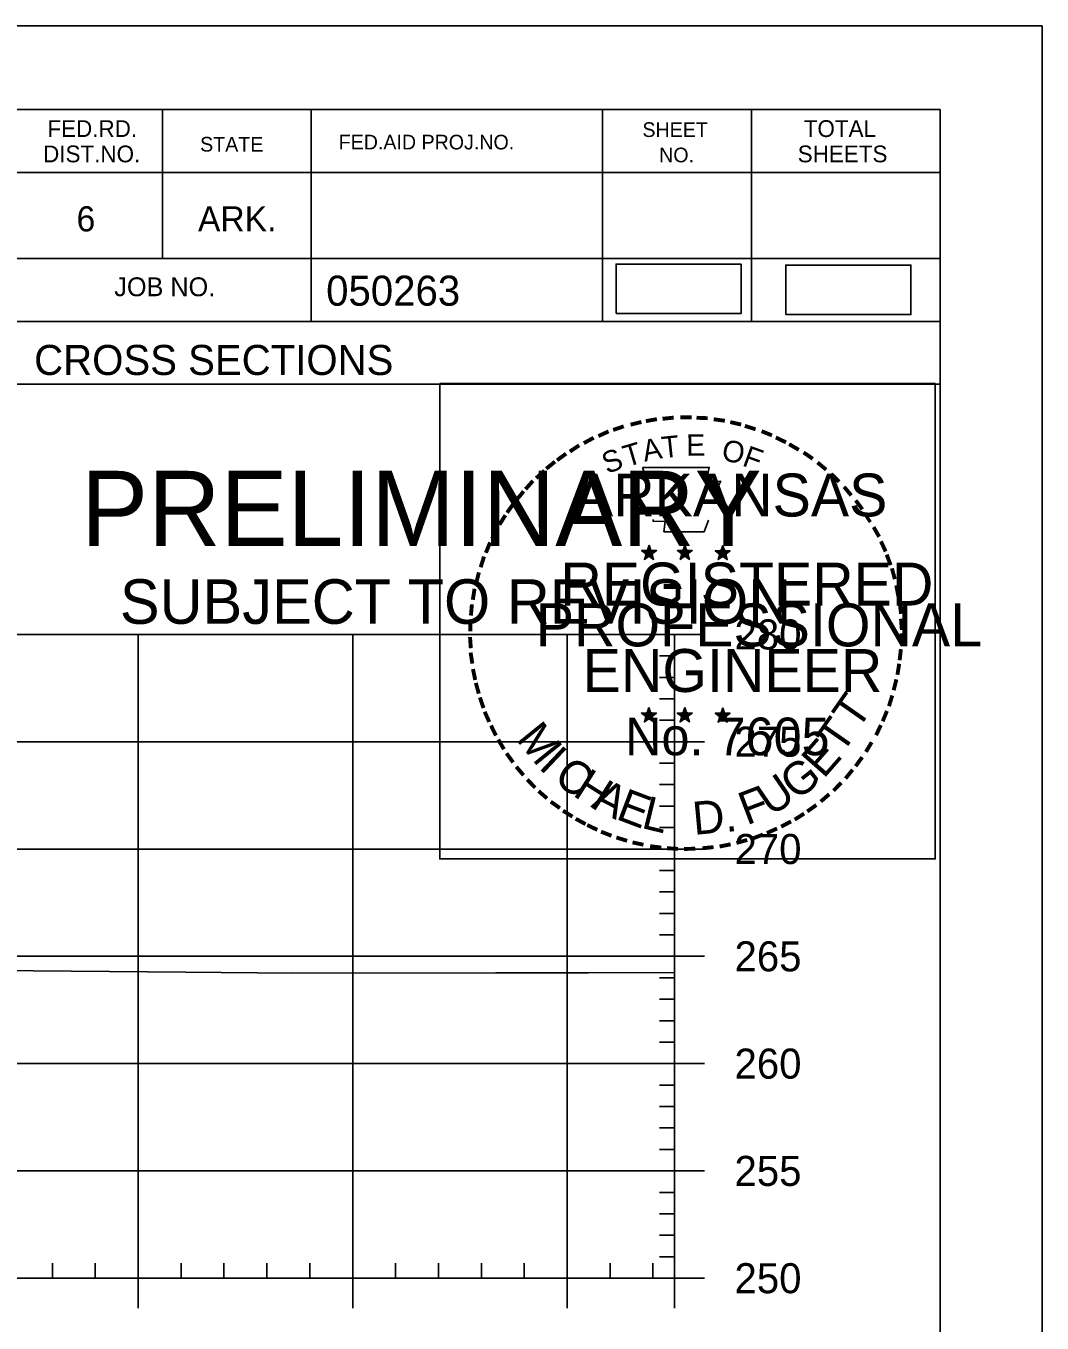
# Model space of a CAD drawing. Extents: x 1365647 to 1367999, y 387113 to 400173.
# Drawn here: x 1366009.7 to 1366057, y 388379 to 388439.4 of the extents above; entities that cross this region are included whole.
import ezdxf

# ---------------------------------------------------------------- set-up
doc = ezdxf.new("R2010")
doc.units = 0
for name, color, linetype in [('R_Axis', 7, 'Continuous'), ('R_Axis Annot', 7, 'Continuous'), ('R_Border', 7, 'Continuous'), ('R_Border PE', 7, 'Continuous'), ('R_Border Prem', 7, 'Continuous'), ('R_Detour', 7, 'Continuous'), ('R_Exist Surface', 7, 'Continuous'), ('R_Grid', 7, 'Continuous'), ('R_No Plot', 7, 'Continuous')]:
    doc.layers.add(name, color=color, linetype=linetype)

msp = doc.modelspace()

# ---------------------------------------------------------------- linework, layer by layer
at = {"layer": 'R_Axis'}
for p, q in [((1366039.888, 388381.069), (1366039.888, 388411.069)), ((1366041.288, 388411.069), (1366039.888, 388411.069)), ((1366039.888, 388410.069), (1366039.188, 388410.069)), ((1366039.888, 388409.069), (1366039.188, 388409.069)), ((1366039.888, 388408.069), (1366039.188, 388408.069)), ((1366039.888, 388407.069), (1366039.188, 388407.069)), ((1366041.288, 388406.069), (1366039.888, 388406.069)), ((1366039.888, 388405.069), (1366039.188, 388405.069)), ((1366039.888, 388404.069), (1366039.188, 388404.069)), ((1366039.888, 388403.069), (1366039.188, 388403.069)), ((1366039.888, 388402.069), (1366039.188, 388402.069)), ((1366041.288, 388401.069), (1366039.888, 388401.069)), ((1366039.888, 388400.069), (1366039.188, 388400.069)), ((1366039.888, 388399.069), (1366039.188, 388399.069)), ((1366039.888, 388398.069), (1366039.188, 388398.069)), ((1366039.888, 388397.069), (1366039.188, 388397.069)), ((1366041.288, 388396.069), (1366039.888, 388396.069)), ((1366039.888, 388395.069), (1366039.188, 388395.069)), ((1366039.888, 388394.069), (1366039.188, 388394.069)), ((1366039.888, 388393.069), (1366039.188, 388393.069)), ((1366039.888, 388392.069), (1366039.188, 388392.069)), ((1366041.288, 388391.069), (1366039.888, 388391.069)), ((1366039.888, 388390.069), (1366039.188, 388390.069)), ((1366039.888, 388389.069), (1366039.188, 388389.069)), ((1366039.888, 388388.069), (1366039.188, 388388.069)), ((1366039.888, 388387.069), (1366039.188, 388387.069)), ((1366041.288, 388386.069), (1366039.888, 388386.069)), ((1366039.888, 388385.069), (1366039.188, 388385.069)), ((1366039.888, 388384.069), (1366039.188, 388384.069)), ((1366039.888, 388383.069), (1366039.188, 388383.069)), ((1366039.888, 388382.069), (1366039.188, 388382.069)), ((1366010.888, 388381.069), (1366010.888, 388381.769)), ((1366012.888, 388381.069), (1366012.888, 388381.769)), ((1366016.888, 388381.069), (1366016.888, 388381.769)), ((1366018.888, 388381.069), (1366018.888, 388381.769)), ((1366020.888, 388381.069), (1366020.888, 388381.769)), ((1366022.888, 388381.069), (1366022.888, 388381.769)), ((1366026.888, 388381.069), (1366026.888, 388381.769)), ((1366028.888, 388381.069), (1366028.888, 388381.769)), ((1366030.888, 388381.069), (1366030.888, 388381.769)), ((1366032.888, 388381.069), (1366032.888, 388381.769)), ((1366036.888, 388381.069), (1366036.888, 388381.769)), ((1366038.888, 388381.069), (1366038.888, 388381.769)), ((1365749.888, 388381.069), (1366039.888, 388381.069)), ((1366014.888, 388379.669), (1366014.888, 388381.069)), ((1366024.888, 388379.669), (1366024.888, 388381.069)), ((1366034.888, 388379.669), (1366034.888, 388381.069)), ((1366039.888, 388379.669), (1366039.888, 388381.069)), ((1366041.288, 388381.069), (1366039.888, 388381.069))]:
    msp.add_line(p, q, dxfattribs=at)
at = {"layer": 'R_Border'}
for p, q in [((1365736.095, 388435.529), (1366052.275, 388435.529)), ((1366016.015, 388435.529), (1366016.015, 388428.589)), ((1366022.955, 388435.529), (1366022.955, 388425.649)), ((1366036.535, 388435.529), (1366036.535, 388425.649)), ((1366043.475, 388435.529), (1366043.475, 388425.649)), ((1366052.275, 388230.069), (1366052.275, 388435.529)), ((1366052.275, 388432.589), (1366009.175, 388432.589)), ((1366052.275, 388432.609), (1366052.275, 388432.609)), ((1366052.275, 388428.589), (1366009.175, 388428.589)), ((1366012.135, 388428.589), (1366052.275, 388428.589)), ((1366052.275, 388425.649), (1365970.015, 388425.649)), ((1366009.175, 388422.729), (1366052.275, 388422.729))]:
    msp.add_line(p, q, dxfattribs=at)
at = {"layer": 'R_Border PE'}
for p, q in [((1366038.705, 388415.229), (1366038.664, 388414.977)), ((1366038.705, 388414.864), (1366038.705, 388415.229)), ((1366038.705, 388415.229), (1366038.754, 388414.979)), ((1366040.375, 388415.229), (1366040.334, 388414.977)), ((1366040.375, 388414.864), (1366040.375, 388415.229)), ((1366040.375, 388415.229), (1366040.424, 388414.979)), ((1366042.139, 388415.217), (1366042.098, 388414.965)), ((1366042.139, 388414.852), (1366042.139, 388415.217)), ((1366042.139, 388415.217), (1366042.188, 388414.967)), ((1366038.356, 388414.975), (1366038.705, 388414.864)), ((1366038.356, 388414.975), (1366038.609, 388414.93)), ((1366038.356, 388414.975), (1366038.593, 388414.853)), ((1366038.489, 388414.567), (1366038.705, 388414.864)), ((1366038.489, 388414.567), (1366038.615, 388414.811)), ((1366038.489, 388414.567), (1366038.703, 388414.784)), ((1366038.918, 388414.567), (1366038.703, 388414.781)), ((1366039.052, 388414.975), (1366038.705, 388414.864)), ((1366038.918, 388414.567), (1366038.705, 388414.864)), ((1366039.052, 388414.975), (1366038.766, 388414.926)), ((1366038.918, 388414.567), (1366038.781, 388414.858)), ((1366039.052, 388414.975), (1366038.848, 388414.873)), ((1366040.026, 388414.975), (1366040.375, 388414.864)), ((1366040.026, 388414.975), (1366040.279, 388414.93)), ((1366040.026, 388414.975), (1366040.263, 388414.853)), ((1366040.159, 388414.567), (1366040.375, 388414.864)), ((1366040.159, 388414.567), (1366040.285, 388414.811)), ((1366040.159, 388414.567), (1366040.373, 388414.784)), ((1366040.588, 388414.567), (1366040.373, 388414.781)), ((1366040.722, 388414.975), (1366040.375, 388414.864)), ((1366040.588, 388414.567), (1366040.375, 388414.864)), ((1366040.722, 388414.975), (1366040.436, 388414.926)), ((1366040.588, 388414.567), (1366040.451, 388414.858)), ((1366040.722, 388414.975), (1366040.518, 388414.873)), ((1366041.79, 388414.963), (1366042.139, 388414.852)), ((1366041.79, 388414.963), (1366042.043, 388414.918)), ((1366041.79, 388414.963), (1366042.027, 388414.841)), ((1366041.923, 388414.555), (1366042.139, 388414.852)), ((1366041.923, 388414.555), (1366042.049, 388414.799)), ((1366041.923, 388414.555), (1366042.137, 388414.772)), ((1366042.352, 388414.555), (1366042.137, 388414.769)), ((1366042.486, 388414.963), (1366042.139, 388414.852)), ((1366042.352, 388414.555), (1366042.139, 388414.852)), ((1366042.486, 388414.963), (1366042.2, 388414.914)), ((1366042.352, 388414.555), (1366042.215, 388414.846)), ((1366042.486, 388414.963), (1366042.282, 388414.861)), ((1366038.352, 388407.402), (1366038.701, 388407.291)), ((1366038.352, 388407.402), (1366038.605, 388407.357)), ((1366038.352, 388407.402), (1366038.589, 388407.28)), ((1366038.701, 388407.656), (1366038.66, 388407.404)), ((1366038.701, 388407.291), (1366038.701, 388407.656)), ((1366038.701, 388407.656), (1366038.75, 388407.406)), ((1366039.048, 388407.402), (1366038.701, 388407.291)), ((1366039.048, 388407.402), (1366038.762, 388407.353)), ((1366039.048, 388407.402), (1366038.844, 388407.3)), ((1366040.021, 388407.402), (1366040.37, 388407.291)), ((1366040.021, 388407.402), (1366040.274, 388407.357)), ((1366040.021, 388407.402), (1366040.258, 388407.28)), ((1366040.37, 388407.656), (1366040.329, 388407.404)), ((1366040.37, 388407.291), (1366040.37, 388407.656)), ((1366040.37, 388407.656), (1366040.419, 388407.406)), ((1366040.717, 388407.402), (1366040.37, 388407.291)), ((1366040.717, 388407.402), (1366040.431, 388407.353)), ((1366040.717, 388407.402), (1366040.513, 388407.3)), ((1366041.788, 388407.392), (1366042.137, 388407.281)), ((1366041.788, 388407.392), (1366042.041, 388407.347)), ((1366041.788, 388407.392), (1366042.025, 388407.27)), ((1366042.137, 388407.646), (1366042.096, 388407.394)), ((1366042.137, 388407.281), (1366042.137, 388407.646)), ((1366042.137, 388407.646), (1366042.186, 388407.396)), ((1366042.484, 388407.392), (1366042.137, 388407.281)), ((1366042.484, 388407.392), (1366042.198, 388407.343)), ((1366042.484, 388407.392), (1366042.28, 388407.29)), ((1366038.485, 388406.994), (1366038.701, 388407.291)), ((1366038.485, 388406.994), (1366038.611, 388407.238)), ((1366038.485, 388406.994), (1366038.699, 388407.211)), ((1366038.914, 388406.994), (1366038.699, 388407.208)), ((1366038.914, 388406.994), (1366038.701, 388407.291)), ((1366038.914, 388406.994), (1366038.777, 388407.285)), ((1366040.154, 388406.994), (1366040.37, 388407.291)), ((1366040.154, 388406.994), (1366040.28, 388407.238)), ((1366040.154, 388406.994), (1366040.368, 388407.211)), ((1366040.583, 388406.994), (1366040.368, 388407.208)), ((1366040.583, 388406.994), (1366040.37, 388407.291)), ((1366040.583, 388406.994), (1366040.446, 388407.285)), ((1366041.921, 388406.984), (1366042.137, 388407.281)), ((1366041.921, 388406.984), (1366042.047, 388407.228)), ((1366041.921, 388406.984), (1366042.135, 388407.201)), ((1366042.35, 388406.984), (1366042.135, 388407.198)), ((1366042.35, 388406.984), (1366042.137, 388407.281)), ((1366042.35, 388406.984), (1366042.213, 388407.275))]:
    msp.add_line(p, q, dxfattribs=at)
for points in [[(1366038.397, 388418.853), (1366038.666, 388418.026)], [(1366041.908, 388417.931), (1366042.05, 388418.215), (1366041.365, 388418.191), (1366041.513, 388418.853), (1366038.397, 388418.853)], [(1366038.889, 388416.43), (1366038.889, 388416.343), (1366039.452, 388416.324), (1366039.398, 388415.851), (1366041.268, 388415.851), (1366041.469, 388416.387)], [(1366038.705, 388415.229), (1366038.918, 388414.567), (1366038.356, 388414.975), (1366039.052, 388414.975), (1366038.489, 388414.567), (1366038.705, 388415.229)], [(1366040.375, 388415.229), (1366040.588, 388414.567), (1366040.026, 388414.975), (1366040.722, 388414.975), (1366040.159, 388414.567), (1366040.375, 388415.229)], [(1366042.139, 388415.217), (1366042.352, 388414.555), (1366041.79, 388414.963), (1366042.486, 388414.963), (1366041.923, 388414.555), (1366042.139, 388415.217)], [(1366038.701, 388407.656), (1366038.914, 388406.994), (1366038.352, 388407.402), (1366039.048, 388407.402), (1366038.485, 388406.994), (1366038.701, 388407.656)], [(1366040.37, 388407.656), (1366040.583, 388406.994), (1366040.021, 388407.402), (1366040.717, 388407.402), (1366040.154, 388406.994), (1366040.37, 388407.656)], [(1366042.137, 388407.646), (1366042.35, 388406.984), (1366041.788, 388407.392), (1366042.484, 388407.392), (1366041.921, 388406.984), (1366042.137, 388407.646)]]:
    msp.add_lwpolyline(points, dxfattribs=at)
for centre, radius in [((1366038.704, 388414.864), 0.172), ((1366038.704, 388414.864), 0.145), ((1366038.704, 388414.864), 0.116), ((1366038.704, 388414.864), 0.0991), ((1366038.704, 388414.864), 0.0747), ((1366038.704, 388414.864), 0.0495), ((1366038.704, 388414.864), 0.0296), ((1366040.374, 388414.864), 0.172), ((1366040.374, 388414.864), 0.145), ((1366040.374, 388414.864), 0.116), ((1366040.374, 388414.864), 0.0991), ((1366040.374, 388414.864), 0.0747), ((1366040.374, 388414.864), 0.0495), ((1366040.374, 388414.864), 0.0296), ((1366042.138, 388414.852), 0.172), ((1366042.138, 388414.852), 0.145), ((1366042.138, 388414.852), 0.116), ((1366042.138, 388414.852), 0.0991), ((1366042.138, 388414.852), 0.0747), ((1366042.138, 388414.852), 0.0495), ((1366042.138, 388414.852), 0.0296), ((1366038.7, 388407.291), 0.172), ((1366038.7, 388407.291), 0.145), ((1366038.7, 388407.291), 0.116), ((1366038.7, 388407.291), 0.0991), ((1366038.7, 388407.291), 0.0747), ((1366040.369, 388407.291), 0.172), ((1366040.369, 388407.291), 0.145), ((1366040.369, 388407.291), 0.116), ((1366040.369, 388407.291), 0.0991), ((1366040.369, 388407.291), 0.0747), ((1366042.136, 388407.281), 0.172), ((1366042.136, 388407.281), 0.145), ((1366042.136, 388407.281), 0.116), ((1366042.136, 388407.281), 0.0991), ((1366042.136, 388407.281), 0.0747), ((1366038.7, 388407.291), 0.0495), ((1366038.7, 388407.291), 0.0296), ((1366040.369, 388407.291), 0.0495), ((1366040.369, 388407.291), 0.0296), ((1366042.136, 388407.281), 0.0495), ((1366042.136, 388407.281), 0.0296)]:
    msp.add_circle(centre, radius, dxfattribs=at)
at = {"layer": 'R_Detour'}
for points in [[(1366037.165, 388426.016), (1366042.998, 388426.016), (1366042.998, 388428.326), (1366037.165, 388428.326)], [(1366045.079, 388425.972), (1366050.912, 388425.972), (1366050.912, 388428.283), (1366045.079, 388428.283)]]:
    msp.add_lwpolyline(points, close=True, dxfattribs=at)
at = {"layer": 'R_Exist Surface'}
msp.add_lwpolyline([(1365966.047, 388396.011), (1365972.755, 388395.719), (1365984.344, 388395.517), (1365994.07, 388395.543), (1366000.308, 388395.484), (1366008.209, 388395.415), (1366017.1, 388395.338), (1366022.092, 388395.291), (1366031.564, 388395.303), (1366035.886, 388395.303), (1366039.888, 388395.309)], dxfattribs=at)
at = {"layer": 'R_Grid'}
for p, q in [((1365749.888, 388411.069), (1366039.888, 388411.069)), ((1366014.888, 388381.069), (1366014.888, 388411.069)), ((1366024.888, 388381.069), (1366024.888, 388411.069)), ((1366034.888, 388381.069), (1366034.888, 388411.069)), ((1366039.888, 388381.069), (1366039.888, 388411.069)), ((1365749.888, 388406.069), (1366039.888, 388406.069)), ((1365749.888, 388401.069), (1366039.888, 388401.069)), ((1365749.888, 388396.069), (1366039.888, 388396.069)), ((1365749.888, 388391.069), (1366039.888, 388391.069)), ((1365749.888, 388386.069), (1366039.888, 388386.069)), ((1365749.888, 388381.069), (1366039.888, 388381.069))]:
    msp.add_line(p, q, dxfattribs=at)
at = {"layer": 'R_No Plot'}
msp.add_line((1365723.694, 388439.423), (1366057.027, 388439.423), dxfattribs=at)
for points in [[(1365723.687, 388439.423), (1366057.027, 388439.423), (1366057.027, 388226.086), (1365723.687, 388226.086)], [(1366028.946, 388422.761), (1366052.044, 388422.761), (1366052.044, 388400.611), (1366028.946, 388400.611)]]:
    msp.add_lwpolyline(points, close=True, dxfattribs=at)

# ---------------------------------------------------------------- texts
at = {"layer": 'R_Axis Annot'}
for s, p in [('280', (1366042.688, 388410.369)), ('275', (1366042.688, 388405.369)), ('270', (1366042.688, 388400.369)), ('265', (1366042.688, 388395.369)), ('260', (1366042.688, 388390.369)), ('255', (1366042.688, 388385.369)), ('250', (1366042.688, 388380.369))]:
    msp.add_text(s, height=1.4, dxfattribs=at).set_placement(p)
at = {"layer": 'R_Border'}
for s, height, p in [('FED.RD.', 0.7819, (1366010.655, 388434.249)), ('SHEET', 0.684, (1366038.395, 388434.249)), ('TOTAL', 0.7819, (1366045.915, 388434.249)), ('STATE', 0.684, (1366017.775, 388433.569)), ('FED.AID PROJ.NO.', 0.684, (1366024.235, 388433.669)), ('DIST.NO.', 0.7819, (1366010.455, 388433.069)), ('NO.', 0.684, (1366039.175, 388433.069)), ('SHEETS', 0.7819, (1366045.635, 388433.069)), ('6', 1.172, (1366012.015, 388429.849)), ('ARK.', 1.1723, (1366017.675, 388429.849)), ('JOB NO.', 0.8792, (1366013.775, 388426.829)), ('050263', 1.4, (1366023.651, 388426.388)), ('CROSS SECTIONS', 1.4, (1366010.038, 388423.159))]:
    msp.add_text(s, height=height, rotation=360, dxfattribs=at).set_placement(p)
at = {"layer": 'R_Border PE'}
for s, height, rotation, p in [('-', 1.6, 5.89682, (1366039.302, 388420.493)), ('-', 1.6, 0.18623, (1366040.074, 388420.565)), ('-', 1.6, 357.74304, (1366040.797, 388420.552)), ('-', 1.6, 19.17608, (1366037.145, 388419.98)), ('-', 1.6, 13.63015, (1366037.895, 388420.221)), ('-', 1.6, 10.21935, (1366038.573, 388420.383)), ('-', 1.6, 352.16172, (1366041.541, 388420.496)), ('-', 1.6, 347.20489, (1366042.26, 388420.382)), ('-', 1.6, 342.3362, (1366042.895, 388420.227)), ('-', 1.6, 28.79182, (1366035.878, 388419.394)), ('-', 1.6, 24.30721, (1366036.511, 388419.711)), ('T', 1, 16.4036, (1366037.666, 388418.862)), ('A', 1, 11.21318, (1366038.492, 388419.113)), ('T', 1, 6.02276, (1366039.341, 388419.279)), ('E', 1, 0.83234, (1366040.446, 388419.389)), ('O', 1, 350.4515, (1366042.05, 388419.179)), ('-', 1.6, 337.85509, (1366043.63, 388420.004)), ('-', 1.6, 334.12109, (1366044.261, 388419.733)), ('-', 1.6, 36.23174, (1366034.703, 388418.629)), ('-', 1.6, 34.06357, (1366035.281, 388419.024)), ('S', 1, 21.59401, (1366036.752, 388418.531)), ('F', 1, 340.07066, (1366043.004, 388418.951)), ('-', 1.6, 329.64089, (1366044.84, 388419.45)), ('-', 1.6, 325.86266, (1366045.483, 388419.089)), ('-', 1.6, 38.95066, (1366034.227, 388418.251)), ('-', 1.6, 320.52971, (1366046.093, 388418.663)), ('-', 1.6, 48.42305, (1366033.346, 388417.356)), ('-', 1.6, 42.96224, (1366033.794, 388417.834)), ('ARKANSAS', 2, 360, (1366035.25, 388416.565)), ('-', 1.6, 315.57859, (1366046.692, 388418.175)), ('-', 1.6, 50.61417, (1366032.943, 388416.87)), ('-', 1.6, 309.87973, (1366047.261, 388417.625)), ('-', 1.6, 54.23247, (1366032.53, 388416.303)), ('-', 1.6, 306.65218, (1366047.786, 388417.023)), ('-', 1.6, 58.07063, (1366032.205, 388415.776)), ('-', 1.4, 303.67529, (1366048.272, 388416.455)), ('-', 1.6, 62.87135, (1366031.892, 388415.162)), ('-', 1.6, 299.66835, (1366048.591, 388415.848)), ('-', 1.6, 67.77427, (1366031.633, 388414.551)), ('-', 1.6, 294.66279, (1366048.915, 388415.236)), ('-', 1.6, 72.39447, (1366031.414, 388413.921)), ('DWB', 0.01, 360, (1366038.691, 388414.859)), ('DWB', 0.01, 360, (1366040.361, 388414.859)), ('DWB', 0.01, 360, (1366042.125, 388414.847)), ('-', 1.6, 290.57283, (1366049.172, 388414.659)), ('REGISTERED', 2, 360, (1366034.572, 388412.416)), ('-', 1.6, 285.12326, (1366049.406, 388414.079)), ('-', 1.6, 75.46096, (1366031.217, 388413.207)), ('-', 1.6, 81.20126, (1366031.085, 388412.494)), ('-', 1.6, 280.54934, (1366049.606, 388413.337)), ('-', 1.6, 85.18634, (1366031.009, 388411.803)), ('PROFESSIONAL', 2, 360, (1366033.424, 388410.512)), ('-', 1.6, 276.59616, (1366049.768, 388412.569)), ('-', 1.6, 89.06224, (1366030.984, 388411.102)), ('-', 1.6, 274.33011, (1366049.828, 388411.847)), ('-', 1.6, 269.94067, (1366049.862, 388411.215)), ('-', 1.6, 94.19588, (1366031.019, 388410.377)), ('ENGINEER', 2, 360, (1366035.611, 388408.387)), ('-', 1.6, 263.5172, (1366049.843, 388410.549)), ('-', 1.6, 98.94793, (1366031.091, 388409.71)), ('-', 1.6, 101.71495, (1366031.226, 388408.977)), ('-', 1.6, 260.99529, (1366049.772, 388409.895)), ('-', 1.6, 105.45785, (1366031.388, 388408.382)), ('-', 1.6, 255.7626, (1366049.662, 388409.217)), ('-', 1.6, 109.08742, (1366031.603, 388407.751)), ('T', 1.54, 55.05496, (1366048.42, 388406.556)), ('-', 1.6, 252.86809, (1366049.481, 388408.497)), ('-', 1.6, 114.06432, (1366031.857, 388407.155)), ('-', 1.6, 247.88866, (1366049.258, 388407.824)), ('-', 1.6, 115.72885, (1366032.162, 388406.537)), ('M', 1.54, 308.91747, (1366032.472, 388406.182)), ('No. 7605', 1.757, 360, (1366037.585, 388405.436)), ('DWB', 0.01, 360, (1366038.686, 388407.287)), ('DWB', 0.01, 360, (1366040.355, 388407.285)), ('DWB', 0.01, 360, (1366042.122, 388407.276)), ('T', 1.54, 55.05496, (1366047.689, 388405.436)), ('-', 1.6, 244.61971, (1366048.996, 388407.195)), ('-', 1.6, 120.44712, (1366032.519, 388405.951)), ('E', 1.54, 48.73133, (1366046.843, 388404.309)), ('-', 1.6, 125.89344, (1366032.922, 388405.39)), ('I', 1.54, 316.46364, (1366033.514, 388404.862)), ('-', 1.6, 239.07125, (1366048.602, 388406.443)), ('-', 1.6, 130.71812, (1366033.384, 388404.838)), ('C', 1.54, 324.01974, (1366034.187, 388404.239)), ('G', 1.54, 38.21734, (1366045.59, 388403.289)), ('-', 1.6, 233.84524, (1366048.2, 388405.79)), ('-', 1.6, 134.22381, (1366033.901, 388404.293)), ('H', 1.54, 327.53419, (1366035.097, 388403.584)), ('U', 1.54, 34.40523, (1366044.391, 388402.556)), ('-', 1.6, 231.25377, (1366047.77, 388405.224)), ('-', 1.6, 138.93382, (1366034.426, 388403.829)), ('A', 1.54, 332.55127, (1366035.951, 388403.047)), ('E', 1.54, 339.20679, (1366037.109, 388402.485)), ('F', 1.54, 20.82016, (1366043.254, 388402.162)), ('-', 1.6, 225.76533, (1366047.291, 388404.66)), ('-', 1.6, 144.64634, (1366034.982, 388403.423)), ('L', 1.54, 346.2929, (1366038.301, 388402.061)), ('D.', 1.54, 5.26016, (1366040.804, 388401.724)), ('-', 1.6, 215.73633, (1366046.22, 388403.679)), ('-', 1.6, 221.08509, (1366046.769, 388404.151)), ('-', 1.6, 148.08978, (1366035.543, 388403.052)), ('-', 1.6, 151.57039, (1366036.122, 388402.727)), ('-', 1.6, 212.24909, (1366045.686, 388403.292)), ('-', 1.6, 154.60019, (1366036.644, 388402.48)), ('-', 1.6, 158.56121, (1366037.268, 388402.226)), ('-', 1.6, 204.25161, (1366044.504, 388402.627)), ('-', 1.6, 207.35684, (1366045.128, 388402.946)), ('-', 1.6, 162.79826, (1366037.955, 388402.013)), ('-', 1.6, 167.55551, (1366038.67, 388401.849)), ('-', 1.6, 191.28576, (1366042.479, 388401.913)), ('-', 1.6, 195.47429, (1366043.208, 388402.112)), ('-', 1.6, 200.71842, (1366043.885, 388402.354)), ('-', 1.6, 173.11546, (1366039.442, 388401.739)), ('-', 1.6, 176.51827, (1366040.19, 388401.686)), ('-', 1.6, 181.59176, (1366040.934, 388401.705)), ('-', 1.6, 185.81666, (1366041.743, 388401.781))]:
    msp.add_text(s, height=height, rotation=rotation, dxfattribs=at).set_placement(p)
at = {"layer": 'R_Border Prem'}
for s, height, p in [('PRELIMINARY', 3.5, (1366012.226, 388415.192)), ('DWB', 0.01, (1366012.973, 388417.041)), ('SUBJECT TO REVISION', 2.07511, (1366014.035, 388411.563))]:
    msp.add_text(s, height=height, rotation=360, dxfattribs=at).set_placement(p)

doc.saveas('drawing.dxf')
